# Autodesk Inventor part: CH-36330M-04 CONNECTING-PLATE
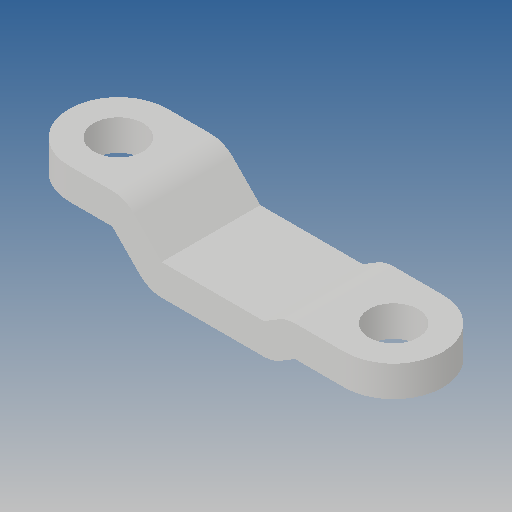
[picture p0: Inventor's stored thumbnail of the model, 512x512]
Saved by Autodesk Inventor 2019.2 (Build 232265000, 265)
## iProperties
Created: 2012-09
Part Number: CH-36330M-04 CONNECTING-PLATE
Material: Ogólny
Document SubType Name: Modeling
Designer: CADENGINEERING4
Density: 1 g/cm^3
Appearance: Domyślna
Author: CADENGINEERING4
Revision Number: ÈÎºÎ
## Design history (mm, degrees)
feature "ÇÐ³ý-À­Éì1"
node "Bryła1"
